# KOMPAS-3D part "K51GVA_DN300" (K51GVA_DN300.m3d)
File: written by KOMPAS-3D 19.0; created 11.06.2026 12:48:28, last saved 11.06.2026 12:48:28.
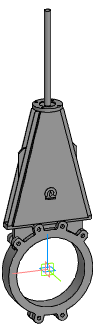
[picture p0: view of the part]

Document properties: Автор: Энергия; Полное имя файла: Z:\3.Личные\kachalov\001_3d для проектировщиков\2.6 Тип_K51GVA. Задвижка\_stp\_stp_K51GVA_DN50-DN1000_с фланцем\K51GVA_DN300.m3d

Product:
- Part/product: K51GVA_DN300

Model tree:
1. Операция без истории:1  (labels: K51GVA_DN300)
